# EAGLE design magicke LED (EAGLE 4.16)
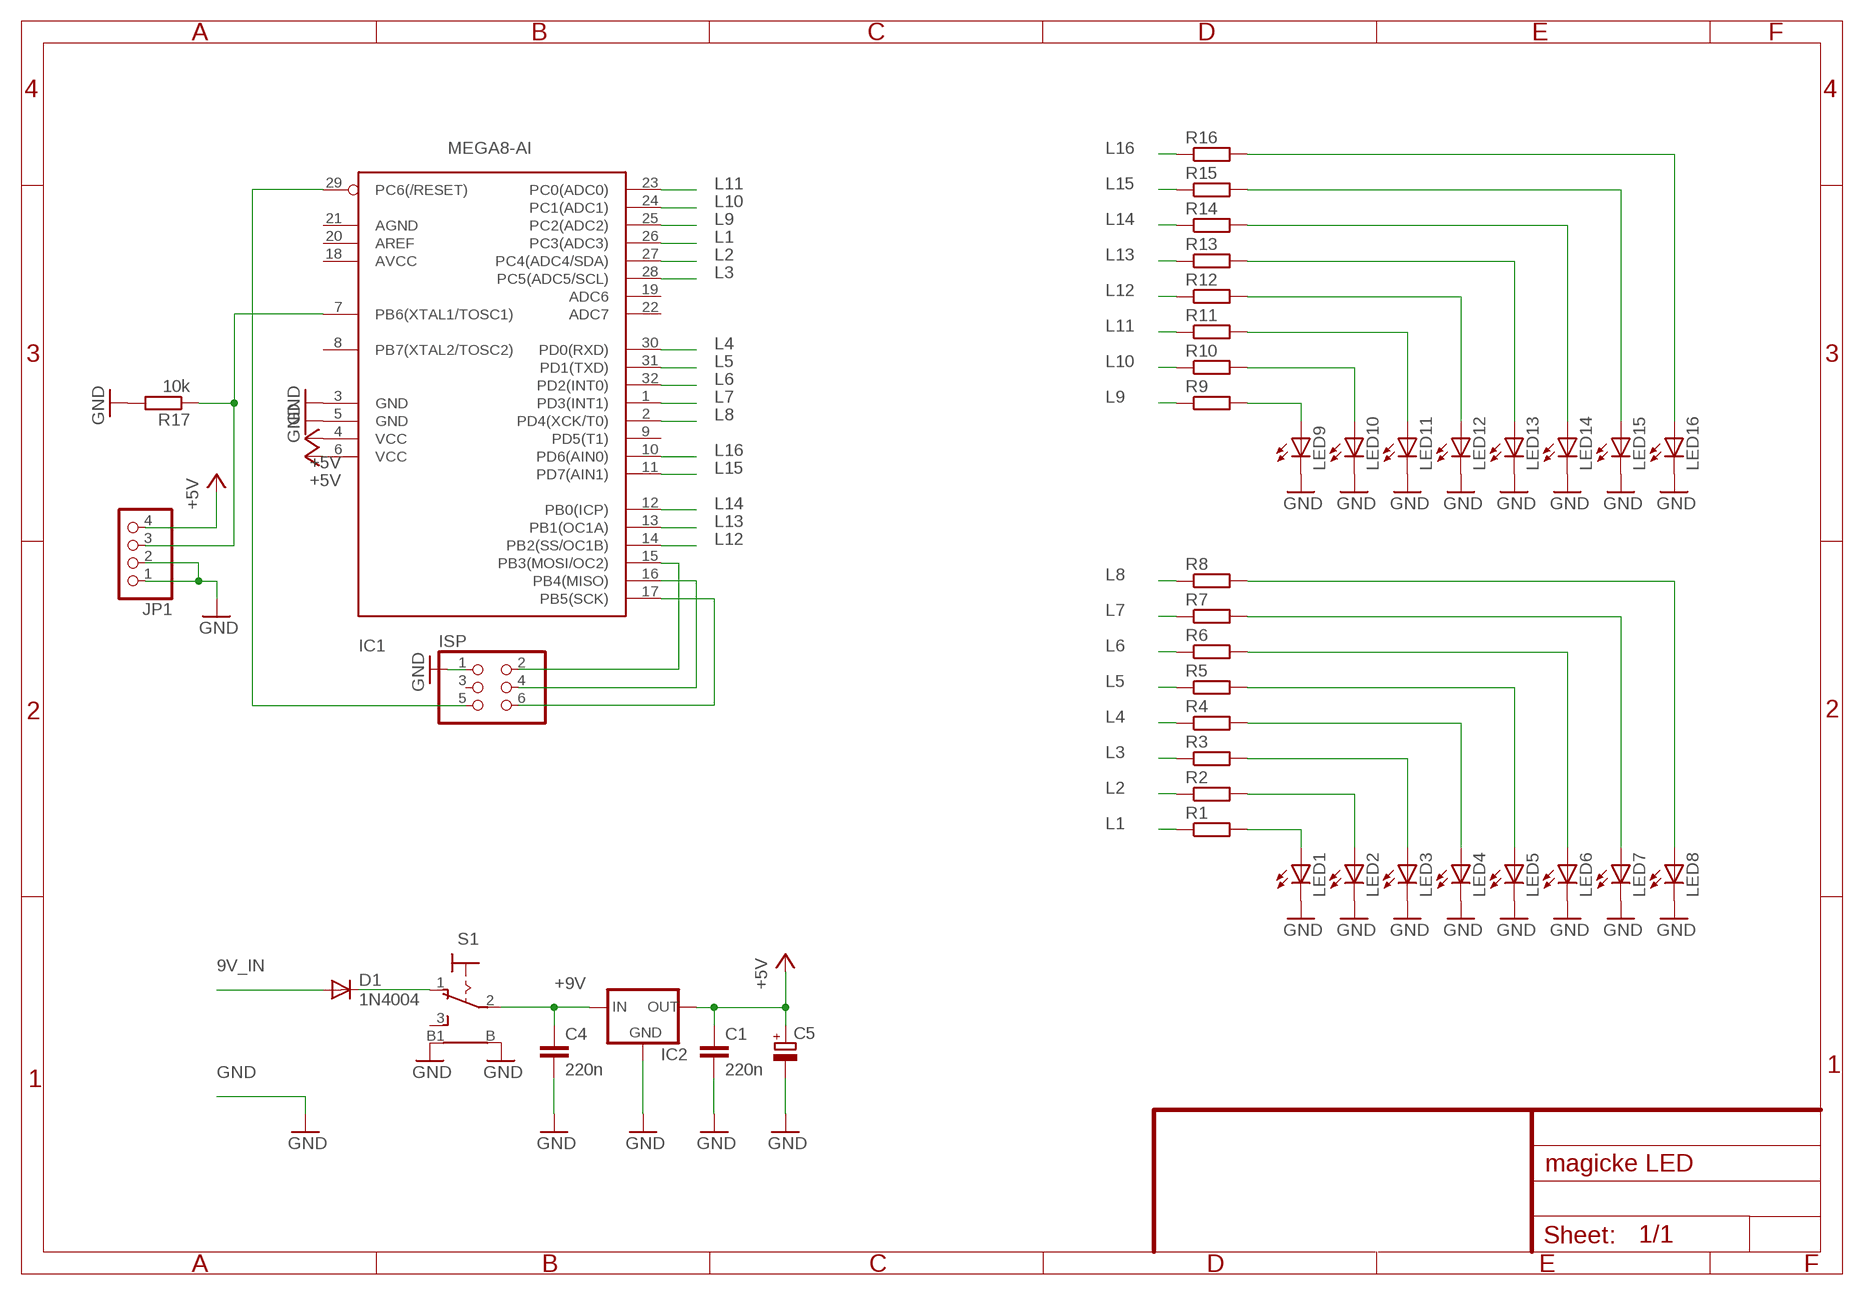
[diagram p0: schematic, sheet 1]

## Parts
C1  220n  C-EUC1206  [C1206]
C4  220n  C-EUC1206  [C1206]
C5  CPOL-EUE2.5-7  [E2,5-7]
D1  1N4004  [DO41-10]
IC1  MEGA8-AI  [TQFP32-08]
IC2  78LXX  [78LXX]
ISP  PINHD-2X3  [2X03]
JP1  PINHD-1X4  [1X04]
LED1  LEDCHIPLED_1206  [CHIPLED_1206]
LED2  LEDCHIPLED_1206  [CHIPLED_1206]
LED3  LEDCHIPLED_1206  [CHIPLED_1206]
LED4  LEDCHIPLED_1206  [CHIPLED_1206]
LED5  LEDCHIPLED_1206  [CHIPLED_1206]
LED6  LEDCHIPLED_1206  [CHIPLED_1206]
LED7  LEDCHIPLED_1206  [CHIPLED_1206]
LED8  LEDCHIPLED_1206  [CHIPLED_1206]
LED9  LEDCHIPLED_1206  [CHIPLED_1206]
LED10  LEDCHIPLED_1206  [CHIPLED_1206]
LED11  LEDCHIPLED_1206  [CHIPLED_1206]
LED12  LEDCHIPLED_1206  [CHIPLED_1206]
LED13  LEDCHIPLED_1206  [CHIPLED_1206]
LED14  LEDCHIPLED_1206  [CHIPLED_1206]
LED15  LEDCHIPLED_1206  [CHIPLED_1206]
LED16  LEDCHIPLED_1206  [CHIPLED_1206]
R1  R-EU_R0805  [R0805]
R2  R-EU_R0805  [R0805]
R3  R-EU_R0805  [R0805]
R4  R-EU_R0805  [R0805]
R5  R-EU_R0805  [R0805]
R6  R-EU_R0805  [R0805]
R7  R-EU_R0805  [R0805]
R8  R-EU_R0805  [R0805]
R9  R-EU_R0805  [R0805]
R10  R-EU_R0805  [R0805]
R11  R-EU_R0805  [R0805]
R12  R-EU_R0805  [R0805]
R13  R-EU_R0805  [R0805]
R14  R-EU_R0805  [R0805]
R15  R-EU_R0805  [R0805]
R16  R-EU_R0805  [R0805]
R17  10k  R-EU_R0805  [R0805]
S1  9070-1W  [9070-1W]

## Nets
9V_IN: D1.A
+5V: C1.1 C5.+ IC1.4(VCC) IC1.6(VCC) IC2.OUT JP1.4
+9V: C4.1 IC2.IN S1.2(P)
GND: C1.2 C4.2 C5.- IC1.3(GND) IC1.5(GND) IC2.GND ISP.1 JP1.1 JP1.2 LED1.C LED2.C LED3.C LED4.C LED5.C LED6.C LED7.C LED8.C LED9.C LED10.C LED11.C LED12.C LED13.C LED14.C LED15.C LED16.C R17.2 S1.B S1.B1
L1: IC1.26(PC3(ADC3)) R1.1
L2: IC1.27(PC4(ADC4/SDA)) R2.1
L3: IC1.28(PC5(ADC5/SCL)) R3.1
L4: IC1.30(PD0(RXD)) R4.1
L5: IC1.31(PD1(TXD)) R5.1
L6: IC1.32(PD2(INT0)) R6.1
L7: IC1.1(PD3(INT1)) R7.1
L8: IC1.2(PD4(XCK/T0)) R8.1
L9: IC1.25(PC2(ADC2)) R9.1
L10: IC1.24(PC1(ADC1)) R10.1
L11: IC1.23(PC0(ADC0)) R11.1
L12: IC1.14(PB2(SS/OC1B)) R12.1
L13: IC1.13(PB1(OC1A)) R13.1
L14: IC1.12(PB0(ICP)) R14.1
L15: IC1.11(PD7(AIN1)) R15.1
L16: IC1.10(PD6(AIN0)) R16.1
N$2: D1.C S1.1(O)
N$3: IC1.7(PB6(XTAL1/TOSC1)) JP1.3 R17.1
N$12: IC1.15(PB3(MOSI/OC2)) ISP.2
N$13: IC1.16(PB4(MISO)) ISP.4
N$15: IC1.17(PB5(SCK)) ISP.6
N$23: LED1.A R1.2
N$24: LED2.A R2.2
N$25: LED3.A R3.2
N$26: LED4.A R4.2
N$27: LED5.A R5.2
N$28: LED6.A R6.2
N$29: LED7.A R7.2
N$30: IC1.29(PC6(/RESET)) ISP.5
N$31: LED8.A R8.2
N$32: LED9.A R9.2
N$33: LED11.A R11.2
N$34: LED10.A R10.2
N$35: LED16.A R16.2
N$36: LED15.A R15.2
N$37: LED14.A R14.2
N$38: LED13.A R13.2
N$39: LED12.A R12.2
Unconnected: IC1.8(PB7(XTAL2/TOSC2)) IC1.9(PD5(T1)) IC1.18(AVCC) IC1.19(ADC6) IC1.20(AREF) IC1.21(AGND) IC1.22(ADC7) ISP.3 S1.3(S)

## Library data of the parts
C1 C4 = rcl:C-EU: CAPACITOR, European symbol
C5 = rcl:CPOL-EU: POLARIZED CAPACITOR, European symbol
D1 = diode:1N4004: DIODE
IC1 = atmel:MEGA8: MICROCONTROLLER 8 Kbytes FLASH 1 kbytes SRAM 512 bytes EEPROM USART 6-channel 10 bit ADC 2-channel 8 bit ADC Source: avr.lbr
IC2 = v-reg:78LXX: VOLTAGE REGULATOR
ISP = pinhead:PINHD-2X3: PIN HEADER
JP1 = pinhead:PINHD-1X4: PIN HEADER
LED1-LED16 = led:LED: LED
R1-R17 = rcl:R-EU_: RESISTOR, European symbol
S1 = switch:9070-1W: TOGGLE SWITCH Marquardt

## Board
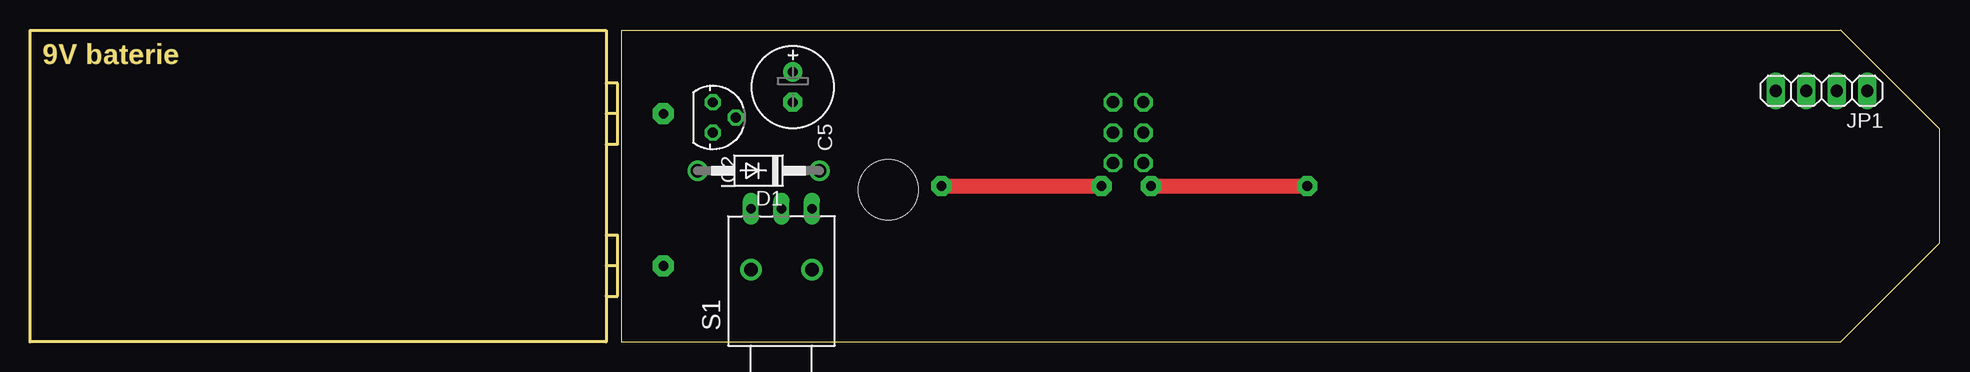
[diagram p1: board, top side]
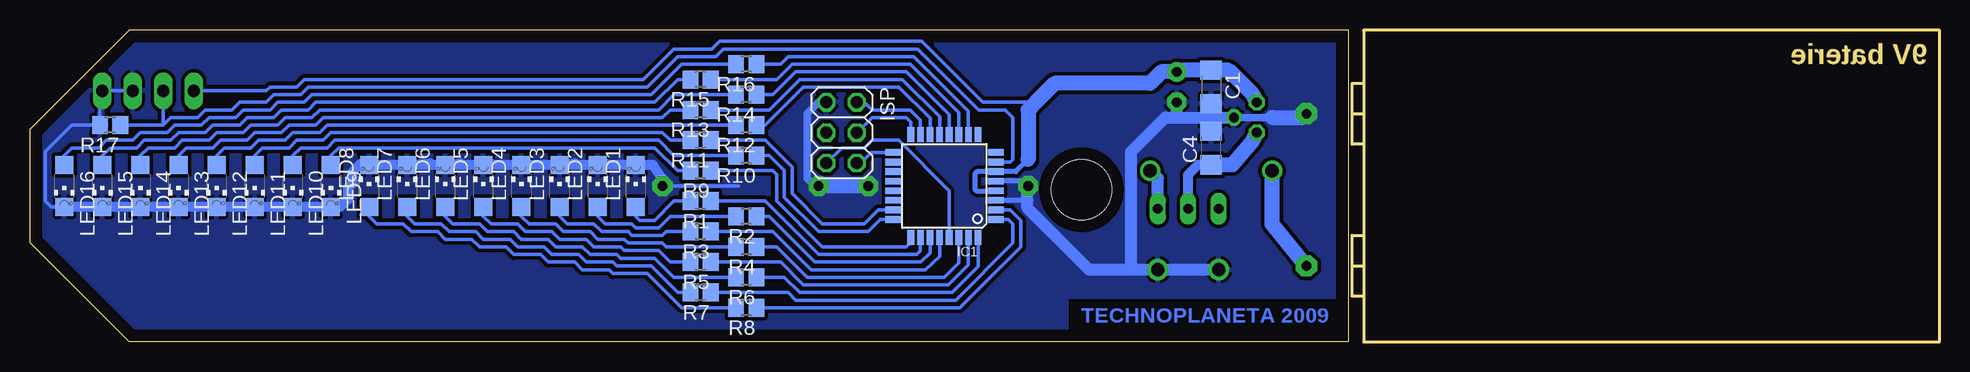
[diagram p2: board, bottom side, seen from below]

Size 159.14 x 26.04 mm. Coordinates in mm from the lower left corner, seen from the top.
Outline: 48.97,19.05 48.01,19.05
Outline: 48.97,6.35 48.01,6.35
Outline: 48.01,3.81 48.97,3.81 48.97,6.35
Outline: 48.97,6.35 48.97,8.89 48.01,8.89
Outline: 48.01,16.51 48.97,16.51 48.97,21.59 48.01,21.59
Outline: 159.14,8.26 159.14,17.78 150.88,26.04 49.29,26.04 49.29,0 150.88,0 159.14,8.26
Outline: 48,0 0,0 0,26 48,26 48,0
Copper layers (1*16): Top 0.035mm / dielectric 1.5mm / Bottom 0.035mm
Design rules "default": minimum track width 10mil, minimum drill 24mil, track to track 8mil, track to pad 8mil, pad to pad 8mil, via to via 8mil, smd to smd 8mil, copper to edge 40mil, drill to drill 8mil, minimum pad ring 10mil, minimum via ring 8mil, stop-mask expansion 4mil, vias tented up to drill 0mil, thermal gap 10mil
Holes 5 mm at 71.51,12.7

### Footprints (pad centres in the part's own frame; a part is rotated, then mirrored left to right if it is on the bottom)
C1206 = smd 1.6 x 1.8: 1 -1.4,0; 2 1.4,0
E2,5-7 = drill 0.813 pad 1.6 round: + -1.27,0 | drill 0.813 pad 1.6 octagon: - 1.27,0
DO41-10 = drill 1.118 round: A 5.08,0; C -5.08,0
TQFP32-08 = smd 1.27 x 0.559: 1 -4.293,2.8; 2 -4.293,2; 3 -4.293,1.2; 4 -4.293,0.4; 5 -4.293,-0.4; 6 -4.293,-1.2; 7 -4.293,-2; 8 -4.293,-2.8; 17 4.293,-2.8; 18 4.293,-2; 19 4.293,-1.2; 20 4.293,-0.4; 21 4.293,0.4; 22 4.293,1.2; 23 4.293,2; 24 4.293,2.8 | smd 0.559 x 1.27: 9 -2.8,-4.293; 10 -2,-4.293; 11 -1.2,-4.293; 12 -0.4,-4.293; 13 0.4,-4.293; 14 1.2,-4.293; 15 2,-4.293; 16 2.8,-4.293; 25 2.8,4.293; 26 2,4.293; 27 1.2,4.293; 28 0.4,4.293; 29 -0.4,4.293; 30 -1.2,4.293; 31 -2,4.293; 32 -2.8,4.293
78LXX = drill 0.813 octagon: GND 0,1.905; IN 1.27,0; OUT -1.27,0
2X03 = drill 1.016 octagon: 1 -2.54,-1.27; 2 -2.54,1.27; 3 0,-1.27; 4 0,1.27; 5 2.54,-1.27; 6 2.54,1.27
1X04 = drill 1.016 long: 1 -3.81,0; 2 -1.27,0; 3 1.27,0; 4 3.81,0
CHIPLED_1206 = smd 1.5 x 1.5: A 0,-1.75; C 0,1.75
R0805 = smd 1.3 x 1.5: 1 -0.85,0; 2 0.85,0
9070-1W = drill 0.813 long: 1 5.08,-2.54; 2 5.08,0; 3 5.08,2.54 | drill 1.118 pad 1.778 round: B 0,-2.54; B1 0,2.54

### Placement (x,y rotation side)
C1  60.72,21.27 270 bottom
C4  60.72,16.19 90 bottom
C5  63.57,21.27 270 top
D1  60.72,14.29 180 top
IC1  82.94,13.02 180 bottom
IC2  56.91,18.73 270 top
ISP  91.51,17.46 270 bottom
JP1  149.3,20.95 180 top
LED1  108.66,13.02 0 bottom
LED2  111.83,13.02 0 bottom
LED3  115.01,13.02 0 bottom
LED4  118.18,13.02 0 bottom
LED5  121.36,13.02 0 bottom
LED6  124.53,13.02 0 bottom
LED7  127.71,13.02 0 bottom
LED8  130.88,13.02 0 bottom
LED9  134.06,13.02 180 bottom
LED10  137.23,13.02 180 bottom
LED11  140.41,13.02 180 bottom
LED12  143.58,13.02 180 bottom
LED13  146.76,13.02 180 bottom
LED14  149.93,13.02 180 bottom
LED15  153.11,13.02 180 bottom
LED16  156.28,13.02 180 bottom
R1  103.26,11.75 180 bottom
R2  99.45,10.48 180 bottom
R3  103.26,9.21 180 bottom
R4  99.45,7.94 180 bottom
R5  103.26,6.67 180 bottom
R6  99.45,5.4 180 bottom
R7  103.26,4.13 180 bottom
R8  99.45,2.86 180 bottom
R9  103.26,14.29 180 bottom
R10  99.45,15.56 180 bottom
R11  103.26,16.83 180 bottom
R12  99.45,18.1 180 bottom
R13  103.26,19.37 180 bottom
R14  99.45,20.64 180 bottom
R15  103.26,21.91 180 bottom
R16  99.45,23.18 180 bottom
R17  152.47,18.1 180 bottom
S1  62.62,6.03 90 top

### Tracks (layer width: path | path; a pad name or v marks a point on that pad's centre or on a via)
9V_IN  (via drill 0.8 pad 1.78)
  Bottom 1.27: v52.78,6.35 55.64,9.84 D1.A
+5V
  Bottom 0.305: 75.32,20 79.77,20 84.84,25.08 101.67,25.08 102.31,24.45 105.48,24.45 108.02,21.91 136.28,21.91 136.91,21.27 139.14,21.27 139.46,20.95 JP1.4
  Bottom 0.406: IC1.4 80.25,12.62 80.4,12.76 80.4,14.03 80.22,14.22 IC1.6 76.98,14.22 75.95,15.24
  Bottom 1.27: IC2.OUT 57.22,20.64 59.26,22.67 C1.1 63.13,22.67 C5.+ 64.84,22.54 65.79,21.59 73.73,21.59 75.32,20 75.95,19.37 75.95,15.24
+9V
  Bottom 0.813: C4.1 61.8,14.79 62.62,13.97 S1.2
  Bottom 1.27: IC2.IN 57.22,16.83 58.94,14.79 C4.1
GND  (via drill 0.8 pad 1.68, 0.8 pad 1.78)
  Top 1.27: v75.95,13.02 v89.29,13.02 | v93.42,13.02 v106.43,13.02
  Bottom 0.305: v106.43,13.02 100.08,13.02 | LED16.C 157.39,11.27 157.87,11.75 157.87,15.87 155.65,18.1 R17.2 153.32,19.47 153.11,19.68 JP1.1 JP1.2
  Bottom 0.406: 76.04,13.42 IC1.5 | 76.02,11.82 IC1.3
  Bottom 0.61: IC2.GND 55.64,18.73 | v93.42,13.02 93.42,12.7 94.37,13.65 94.37,19.05 93.42,20 ISP.1
  Bottom 0.813: 60.71,18.73 C4.2 | LED16.C 153.26,11.27 153.11,11.11 LED15.C 150.09,11.27 149.93,11.11 LED14.C 146.91,11.27 146.76,11.11 LED13.C 143.74,11.27 143.58,11.11 | 143.58,11.11 LED12.C | 143.58,11.11 143.43,11.27 LED11.C 137.39,11.27 137.23,11.11 LED10.C 134.21,11.27 134.06,11.11 LED9.C 133.27,11.27 132.66,11.87 132.66,12.83 132.28,13.21 132.28,14.16 131.52,14.92 130.88,14.92 LED8.C 125.96,14.77 125.8,14.92 LED7.C 123.42,14.77 123.26,14.92 LED6.C 120.88,14.77 120.72,14.92 LED5.C 118.34,14.77 118.18,14.92 LED4.C 113.89,14.77 113.74,14.92 LED3.C 111.35,14.77 111.2,14.92 LED2.C 108.81,14.77 108.66,14.92 LED1.C 107.23,14.77 106.43,13.65 v106.43,13.02 | 76.02,12.63 v75.95,13.02
  Bottom 1.016: 60.71,18.73 IC2.GND | 67.38,6.03 70.87,6.03 76.02,11.18 76.02,11.82 76.02,12.63 | 76.04,13.42 75.95,13.34 v75.95,13.02 | 60.71,18.73 C1.2 | 63.57,18.73 60.71,18.73 | 63.57,18.73 C5.- | 63.57,18.73 64.52,18.73 67.38,15.87 67.38,6.03 | S1.B1 S1.B 67.38,6.03
  Bottom 1.27: C4.2 60.71,17.46 | v89.29,13.02 v93.42,13.02 | 55.64,18.73 53.09,18.73 v52.78,19.05
  pour Bottom (isolate 0.305): 47.06,3.81 47.06,27.3 160.41,27.3 160.41,-1.27 72.78,-1.27 72.78,3.81
L1
  Bottom 0.305: IC1.26 84.94,7.59 85.23,7.3 93.42,7.3 97.86,11.75 R1.1
L2
  Bottom 0.305: IC1.27 84.14,7.44 84.91,6.67 93.73,6.67 97.54,10.48 R2.1 98.82,10.48
L3
  Bottom 0.305: R3.1 97.23,9.21 94.05,6.03 84.53,6.03 83.34,7.16 IC1.28
L4
  Bottom 0.305: IC1.30 81.74,6.6 82.94,5.4 94.37,5.4 96.91,7.94 R4.1 98.82,7.94
L5
  Bottom 0.305: IC1.31 80.94,6.45 82.62,4.76 94.69,4.76 96.59,6.67 R5.1
L6
  Bottom 0.305: R6.1 96.28,5.4 95.01,4.13 82.31,4.13 80.14,6.29 IC1.32
L7
  Bottom 0.305: R7.1 95.96,4.13 95.32,3.49 81.99,3.49 77.22,8.26 77.22,9.84 77.6,10.22 IC1.1
L8
  Bottom 0.305: R8.1 81.67,2.86 76.59,7.94 76.59,10.16 77.45,11.02 IC1.2
L9
  Bottom 0.305: IC1.25 85.74,8.31 86.11,7.94 93.1,7.94 96.91,11.75 96.91,13.97 97.23,14.29 R9.1
L10
  Bottom 0.305: 98.82,15.56 R10.1 97.54,15.56 96.28,14.29 96.28,12.07 93.42,9.21 89.29,9.21 88.28,10.22 IC1.24
L11
  Bottom 0.305: R11.1 97.86,16.83 95.64,14.6 95.64,12.38 93.1,9.84 89.61,9.84 88.43,11.02 IC1.23
L12
  Bottom 0.305: IC1.14 84.14,18.66 86.75,21.27 94.69,21.27 97.86,18.1 R12.1
L13
  Bottom 0.305: R13.1 97.54,19.37 95.01,21.91 86.43,21.91 83.34,18.81 IC1.13
L14
  Bottom 0.305: R14.1 97.23,20.64 95.32,22.54 86.11,22.54 82.54,18.97 IC1.12
L15
  Bottom 0.305: R15.1 96.91,21.91 95.64,23.18 85.8,23.18 81.74,19.12 IC1.11
L16
  Bottom 0.305: IC1.10 80.94,19.27 85.48,23.81 95.96,23.81 96.59,23.18 R16.1
N$2
  Bottom 1.016: D1.C 65.16,13.65 S1.1
N$3
  Bottom 0.305: IC1.7 77.45,15.02 77.22,15.24 77.22,18.73 77.86,19.37 80.08,19.37 85.16,24.45 101.36,24.45 101.99,23.81 105.16,23.81 107.71,21.27 135.96,21.27 136.6,20.64 138.82,20.64 139.46,20 141.68,20 142.31,19.37 144.54,19.37 145.17,18.73 147.39,18.73 148.03,18.1 | 148.03,18.1 R17.1 | 148.03,18.1 JP1.3
N$12
  Bottom 0.305: IC1.15 84.94,18.51 85.8,19.37 88.97,19.37 89.61,20 ISP.2
N$13
  Bottom 0.305: IC1.16 85.74,18.36 86.11,18.73 88.97,18.73 ISP.4
N$15
  Bottom 0.305: IC1.17 89.03,15.82 89.93,14.92 ISP.6
N$23
  Bottom 0.305: R1.2 105.48,11.75 107.07,10.16 108.34,10.16 108.66,10.48 LED1.A
N$24
  Bottom 0.305: R2.2 105.8,10.48 106.75,9.52 108.66,9.52 108.97,9.84 111.2,9.84 111.83,10.48 LED2.A
N$25
  Bottom 0.305: R3.2 106.12,9.21 106.43,8.89 108.97,8.89 109.29,9.21 111.51,9.21 112.15,9.84 114.37,9.84 115.01,10.48 LED3.A
N$26
  Bottom 0.305: R4.2 106.12,7.94 106.43,8.26 109.29,8.26 109.61,8.57 111.83,8.57 112.47,9.21 114.69,9.21 115.33,9.84 117.55,9.84 118.18,10.48 LED4.A
N$27
  Bottom 0.305: R5.2 105.8,6.67 106.75,7.62 109.61,7.62 109.93,7.94 112.15,7.94 112.79,8.57 115.01,8.57 115.64,9.21 117.86,9.21 118.5,9.84 120.72,9.84 121.36,10.48 LED5.A
N$28
  Bottom 0.305: R6.2 105.48,5.4 107.07,6.99 109.93,6.99 110.25,7.3 112.47,7.3 113.1,7.94 115.33,7.94 115.96,8.57 118.18,8.57 118.82,9.21 121.04,9.21 121.68,9.84 123.9,9.84 124.53,10.48 LED6.A
N$29
  Bottom 0.305: R7.2 105.16,4.13 107.39,6.35 110.25,6.35 110.56,6.67 112.79,6.67 113.42,7.3 115.64,7.3 116.28,7.94 118.5,7.94 119.14,8.57 121.36,8.57 121.99,9.21 124.21,9.21 124.85,9.84 127.07,9.84 127.71,10.48 LED7.A
N$30
  Bottom 0.305: ISP.5 91.51,16.19 89.61,16.19 88.97,16.83 86.75,16.83 82.54,12.62 IC1.29
N$31
  Bottom 0.305: R8.2 104.85,2.86 107.71,5.71 110.56,5.71 110.88,6.03 113.1,6.03 113.74,6.67 115.96,6.67 116.6,7.3 118.82,7.3 119.45,7.94 121.68,7.94 122.31,8.57 124.53,8.57 125.17,9.21 127.39,9.21 128.02,9.84 130.25,9.84 130.88,10.48 LED8.A
N$32
  Bottom 0.305: R9.2 105.16,14.29 107.07,16.19 133.42,16.19 134.06,15.56 LED9.A
N$33
  Bottom 0.305: R11.2 105.8,16.83 106.43,17.46 134.06,17.46 134.69,16.83 136.91,16.83 137.55,16.19 139.77,16.19 140.41,15.56 LED11.A
N$34
  Bottom 0.305: R10.2 105.48,15.56 106.75,16.83 133.74,16.83 134.38,16.19 136.6,16.19 137.23,15.56 LED10.A
N$35
  Bottom 0.305: R16.2 104.85,23.18 107.39,20.64 135.65,20.64 136.28,20 138.5,20 139.14,19.37 141.36,19.37 141.99,18.73 144.22,18.73 144.85,18.1 147.07,18.1 147.71,17.46 149.93,17.46 150.57,16.83 152.79,16.83 153.43,16.19 155.65,16.19 156.28,15.56 LED16.A
N$36
  Bottom 0.305: R15.2 105.16,21.91 107.07,20 135.33,20 135.96,19.37 138.19,19.37 138.82,18.73 141.04,18.73 141.68,18.1 143.9,18.1 144.54,17.46 146.76,17.46 147.39,16.83 149.61,16.83 150.25,16.19 152.47,16.19 153.11,15.56 LED15.A
N$37
  Bottom 0.305: R14.2 105.48,20.64 106.75,19.37 135.01,19.37 135.65,18.73 137.87,18.73 138.5,18.1 140.72,18.1 141.36,17.46 143.58,17.46 144.22,16.83 146.44,16.83 147.07,16.19 149.3,16.19 149.93,15.56 LED14.A
N$38
  Bottom 0.305: R13.2 105.8,19.37 106.43,18.73 134.69,18.73 135.33,18.1 137.55,18.1 138.19,17.46 140.41,17.46 141.04,16.83 143.27,16.83 143.9,16.19 146.12,16.19 146.76,15.56 LED13.A
N$39
  Bottom 0.305: R12.2 134.38,18.1 135.01,17.46 137.23,17.46 137.87,16.83 140.09,16.83 140.72,16.19 142.95,16.19 143.58,15.56 LED12.A

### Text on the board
Bottom: TECHNOPLANETA 2009
Dimension: 9V baterie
